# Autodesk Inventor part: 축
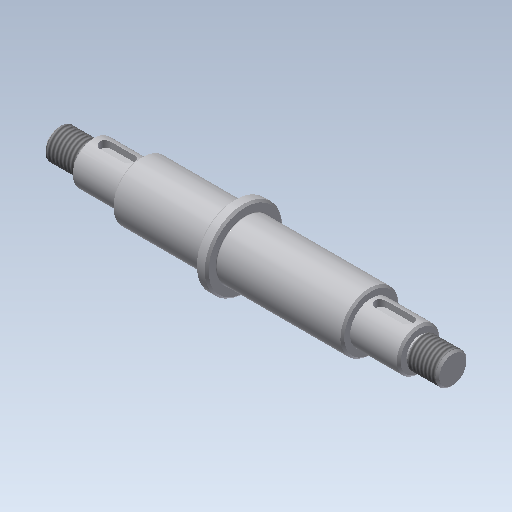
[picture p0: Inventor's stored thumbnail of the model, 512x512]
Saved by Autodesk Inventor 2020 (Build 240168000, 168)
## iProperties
CustomPartVersion: 1
Created: 2021-06
Part Number: 축
Material: 강철, 연강
Document SubType Name: Modeling
Designer: mdu
Density: 1 g/cm^3
Appearance: 흰색
Author: mdu
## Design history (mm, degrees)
sketch "주 스케치"
  geometry: L1 (0, 0)-(203, 0) reference; L2 (0, 0)-(0, 8); L3 (0, 8)-(17, 8); L4 (17, 8)-(17, 11); L5 (17, 11)-(42, 11); L6 (42, 11)-(42, 15); L7 (42, 15)-(90, 15); L8 (90, 15)-(90, 20); L9 (96, 20)-(96, 15); L10 (90, 20)-(96, 20); L11 (161, 15)-(161, 11); L12 (96, 15)-(161, 15); L13 (186, 11)-(186, 8); L14 (161, 11)-(186, 11); L15 (203, 8)-(203, 0); L16 (186, 8)-(203, 8)
  constraints: 32 end point, 9 horizontal, 8 vertical
  dimensions: "d3" = 16 diameter of L3 L1 (derived); "d4" = 22 diameter of L5 L1 (derived); "d5" = 30 diameter of L7 L1 (derived); "d6" = 40 diameter of L10 L1 (derived); "d7" = 30 diameter of L12 L1 (derived); "d8" = 22 diameter of L14 L1 (derived); "d9" = 16 diameter of L16 L1 (derived)
revolve "회전1" sketch "주 스케치" stored, may be unused: angle "d10" = 0 deg
chamfer "모따기1" distance "d11" = 1; stored, may be unused: second distance "d12" = 1, angle "d13" = 45 deg
chamfer "모따기2" distance "d14" = 1; stored, may be unused: second distance "d15" = 1, angle "d16" = 45 deg
node "키홈1"
chamfer "모따기3" distance "d17" = 1; stored, may be unused: second distance "d18" = 1, angle "d19" = 45 deg
fillet "모깎기1" dims "d20" = 0.3
chamfer "모따기4" distance "d21" = 1; stored, may be unused: second distance "d22" = 1, angle "d23" = 45 deg
chamfer "모따기5" distance "d24" = 1; stored, may be unused: second distance "d25" = 1, angle "d26" = 45 deg
fillet "모깎기2" dims "d27" = 0.3
chamfer "모따기6" distance "d28" = 1; stored, may be unused: second distance "d29" = 1, angle "d30" = 45 deg
chamfer "모따기7" distance "d31" = 1; stored, may be unused: second distance "d32" = 1, angle "d33" = 45 deg
node "키홈2"
chamfer "모따기8" distance "d34" = 1; stored, may be unused: second distance "d35" = 1, angle "d36" = 45 deg
sketch "스케치3"
  geometry: L1 (1, 8)-(17, 8) reference; L2 (17, -10)-(17, 10) reference; L3 (186, 10)-(186, -10) reference; L4 (186, 8)-(202, 8) reference; L5 (203, 7)-(203, -7) reference; L6 (0, 0)-(203, 0); L7 (17, 8)-(15.5, 8); L8 (15.5, 8)-(15.5, 7); L9 (15.5, 7)-(17, 7); L10 (17, 7)-(17, 8); L11 (186, 8)-(187.5, 8); L12 (187.5, 8)-(187.5, 7); L13 (187.5, 7)-(186, 7); L14 (186, 7)-(186, 8)
  constraints: 18 end point, 4 parallel, 2 horizontal, 2 perpendicular, 1 midpoint
  dimensions: "d37" = 14 diameter of L13 L6; "d39" = 1.5 distance of L12.end L13.end; "d40" = 14 diameter of L9 L6; "d41" = 1.5 distance of L8.end L9.end
revolve "회전2" sketch "스케치3" stored, may be unused: angle "d42" = 90 deg
feature "스레드1" dims "d43" = 10, "d44" = 0
feature "스레드2" dims "d45" = 10, "d46" = 0
sketch "스케치4"
  geometry: L1 (186, 7)-(186, -7) reference; L2 (186, 10)-(186, -10) reference; L3 (161, -11)-(185, -11) reference; L4 (165, -11)-(165, -9); L5 (165, -9)-(167, -11); L6 (165, -11)-(167, -11); 1 further point
  constraints: 6 end point, 2 point on line, 1 collinear, 1 perpendicular
  dimensions: "d47" = 21 distance from line of L2 L4.start; "d48" = 4 diameter of L5.end L4; "d49" = 45 deg angle of L4 L5
revolve "회전3" sketch "스케치4" stored, may be unused: angle "d50" = 90 deg
node "솔리드1"
feature "iFeature3:1"
feature "iFeature3:2"
node "투영된 루프1"
other parameters: "d0" = 0, "d1" = 0, "d2" = 0
